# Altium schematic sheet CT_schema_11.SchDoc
size 391 x 278 mm
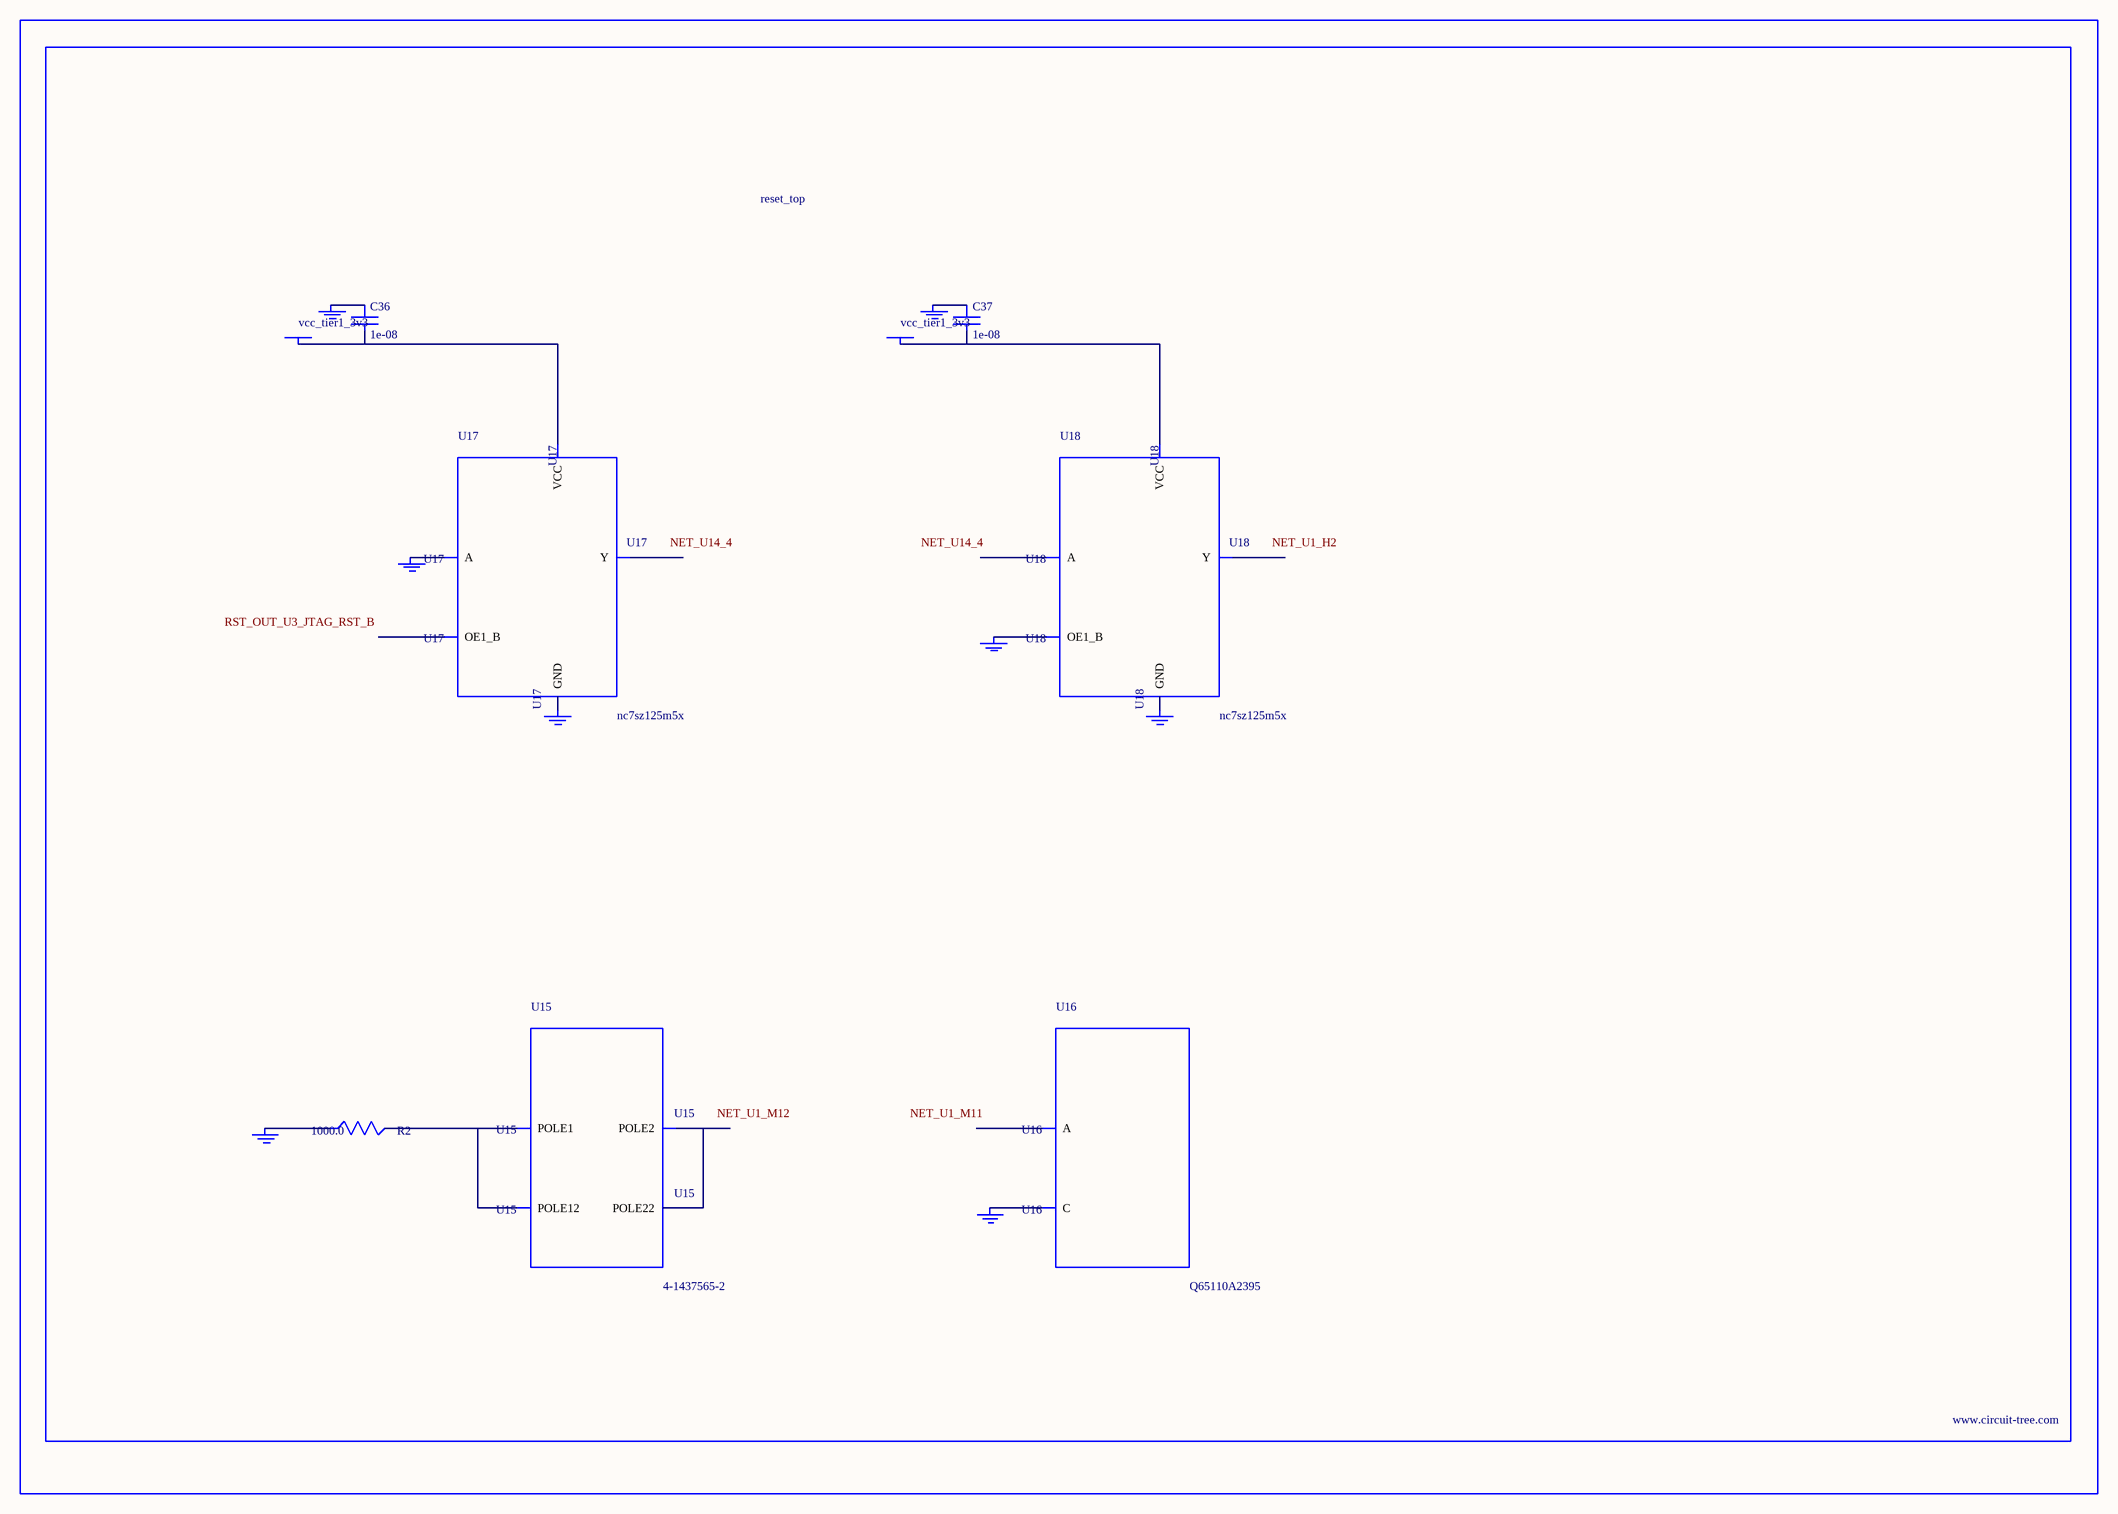
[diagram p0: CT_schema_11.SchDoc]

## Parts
BORDER10  (no value)
C36  1e-08  [C0402]
C37  1e-08  [C0402]
GND_INSTANCE_10_0  (no value)
GND_INSTANCE_10_1  (no value)
GND_INSTANCE_10_2  (no value)
GND_INSTANCE_10_3  (no value)
GND_INSTANCE_10_4  (no value)
GND_INSTANCE_10_5  (no value)
GND_INSTANCE_10_6  (no value)
GND_INSTANCE_10_7  (no value)
POWER_INSTANCE_10_0  vcc_tier1_3v3
POWER_INSTANCE_10_1  vcc_tier1_3v3
R2  1000.0  [R0603]
U15  4-1437565-2  [SW_4-1437565-2]
U16  Q65110A2395  [LGM67K-G1J2-24-Z]
U17  nc7sz125m5x  [NC7SZ125M5X]
U18  nc7sz125m5x  [NC7SZ125M5X]

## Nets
NetC36_1: C36.1 GND_INSTANCE_10_2.0(GND)
NetC36_2: C36.2 POWER_INSTANCE_10_0.0(PWR) U17.5(VCC)
NetC37_1: C37.1 GND_INSTANCE_10_5.0(GND)
NetC37_2: C37.2 POWER_INSTANCE_10_1.0(PWR) U18.5(VCC)
NetGND_INSTANCE_10_0_0: GND_INSTANCE_10_0.0(GND) R2.1
NetGND_INSTANCE_10_1_0: GND_INSTANCE_10_1.0(GND) U16.C
NetGND_INSTANCE_10_3_0: GND_INSTANCE_10_3.0(GND) U17.2(A)
NetGND_INSTANCE_10_4_0: GND_INSTANCE_10_4.0(GND) U17.3(GND)
NetGND_INSTANCE_10_6_0: GND_INSTANCE_10_6.0(GND) U18.1(OE1_B)
NetGND_INSTANCE_10_7_0: GND_INSTANCE_10_7.0(GND) U18.3(GND)
NetR2_2: R2.2 U15.1(POLE1) U15.2(POLE12)
NetU15_3: U15.3(POLE2) U15.4(POLE22)

Not connected (* = marked no-connect by the designer): U16 A; U17 1(OE1_B) 4(Y); U18 2(A) 4(Y)

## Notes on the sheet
- Labels drawn without touching a wire or pin: NET_U1_H2, NET_U1_M11, NET_U1_M12, NET_U14_4, RST_OUT_U3_JTAG_RST_B

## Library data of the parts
BORDER10 = BORDER_PAGE10
C36 C37 = C0402C103K3RAC
GND_INSTANCE_10_0-GND_INSTANCE_10_7 = GND
POWER_INSTANCE_10_0 POWER_INSTANCE_10_1 = PWR
R2 = RC0603JR-071KL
